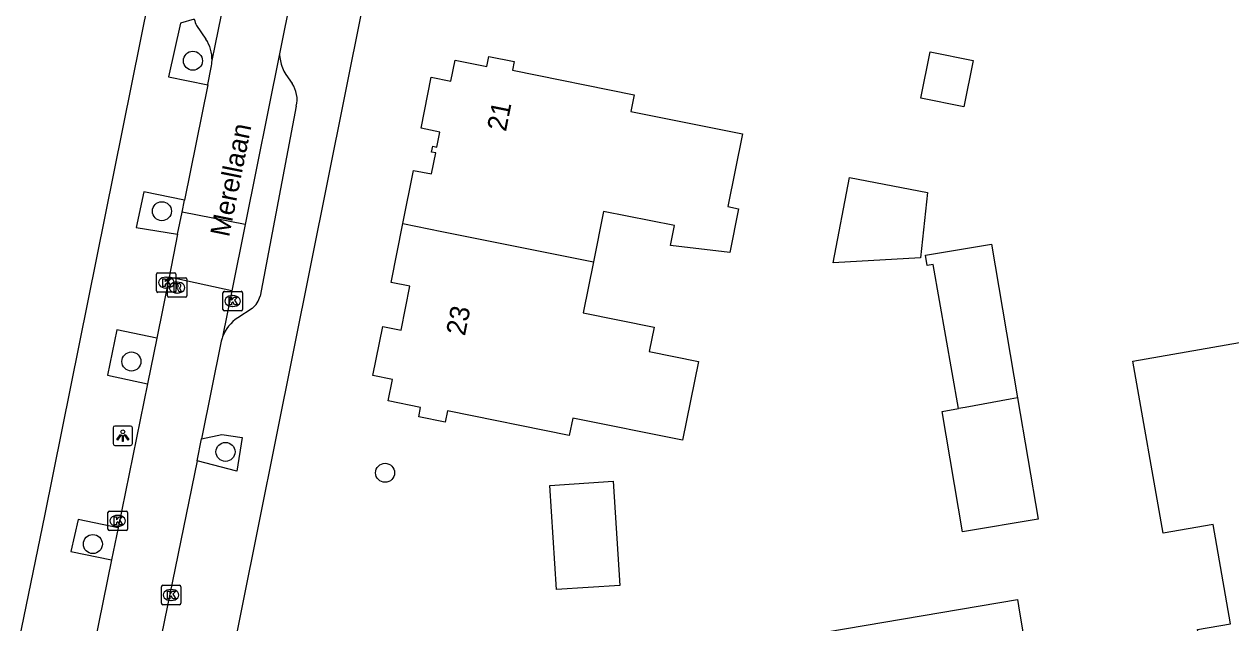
# Model space of a CAD drawing. Extents: x 161772 to 163123, y 383092 to 383917.
# Drawn here: x 162235.6 to 162297.6, y 383662.5 to 383693.3 of the extents above; entities that cross this region are included whole.
import ezdxf

# ---------------------------------------------------------------- set-up
doc = ezdxf.new("R2010")
doc.units = 0
for name, color, linetype in [('IMGEO_Boom', 7, 'Continuous'), ('IMGEO_Kolk', 7, 'Continuous'), ('IMGEO_Lichtpunt', 7, 'Continuous'), ('IMGEO_Openbare_ruimte_label', 7, 'Continuous'), ('IMGEO_Pand', 7, 'Continuous'), ('IMGEO_Pand_nummerreeks', 7, 'Continuous'), ('IMGEO_Parkeervlak_open', 7, 'Continuous'), ('IMGEO_Rijbaan_lokaal_open', 7, 'Continuous'), ('IMGEO_Rioolput', 7, 'Continuous'), ('IMGEO_Voetpad_open', 7, 'Continuous')]:
    doc.layers.add(name, color=color, linetype=linetype)

msp = doc.modelspace()

# ---------------------------------------------------------------- linework, layer by layer
at = {"layer": 'IMGEO_Boom'}
for centre in [(162244.252, 383691.425), (162242.659, 383683.691), (162241.091, 383675.965), (162245.927, 383671.318), (162254.126, 383670.243), (162239.112, 383666.581)]:
    msp.add_circle(centre, 0.489, dxfattribs=at)
at = {"layer": 'IMGEO_Kolk'}
for p, q in [((162242.38, 383679.595), (162242.38, 383680.447)), ((162242.455, 383680.521), (162243.307, 383680.521)), ((162243.381, 383680.447), (162243.381, 383679.595)), ((162242.868, 383680.301), (162242.893, 383680.301)), ((162243.307, 383679.521), (162242.455, 383679.521)), ((162242.891, 383679.741), (162242.866, 383679.741)), ((162245.797, 383678.646), (162245.797, 383679.498)), ((162245.872, 383679.572), (162246.724, 383679.572)), ((162246.285, 383679.352), (162246.31, 383679.352)), ((162246.798, 383679.498), (162246.798, 383678.646)), ((162246.724, 383678.572), (162245.872, 383678.572)), ((162246.308, 383678.792), (162246.283, 383678.792)), ((162239.887, 383667.347), (162239.887, 383668.199)), ((162239.962, 383668.273), (162240.814, 383668.273)), ((162240.375, 383668.053), (162240.4, 383668.053)), ((162240.888, 383668.199), (162240.888, 383667.347)), ((162240.398, 383667.493), (162240.373, 383667.493)), ((162240.814, 383667.273), (162239.962, 383667.273)), ((162242.63, 383663.535), (162242.63, 383664.387)), ((162242.705, 383664.461), (162243.557, 383664.461)), ((162243.631, 383664.387), (162243.631, 383663.535)), ((162243.141, 383663.681), (162243.116, 383663.681)), ((162243.118, 383664.241), (162243.143, 383664.241)), ((162243.557, 383663.461), (162242.705, 383663.461))]:
    msp.add_line(p, q, dxfattribs=at)
for points in [[(162242.38, 383679.595), (162242.38, 383680.447)], [(162242.455, 383680.521), (162243.307, 383680.521)], [(162243.381, 383680.447), (162243.381, 383679.595)], [(162242.701, 383680.221), (162242.824, 383680.221), (162242.824, 383680.07), (162242.954, 383680.221), (162243.118, 383680.221), (162242.972, 383680.07), (162243.125, 383679.821), (162242.973, 383679.821), (162242.888, 383679.985), (162242.824, 383679.918), (162242.824, 383679.821), (162242.701, 383679.821), (162242.701, 383680.221)], [(162243.307, 383679.521), (162242.455, 383679.521)], [(162245.797, 383678.646), (162245.797, 383679.498)], [(162245.872, 383679.572), (162246.724, 383679.572)], [(162246.118, 383679.272), (162246.241, 383679.272), (162246.241, 383679.121), (162246.371, 383679.272), (162246.535, 383679.272), (162246.389, 383679.121), (162246.542, 383678.872), (162246.39, 383678.872), (162246.305, 383679.036), (162246.241, 383678.969), (162246.241, 383678.872), (162246.118, 383678.872), (162246.118, 383679.272)], [(162246.798, 383679.498), (162246.798, 383678.646)], [(162246.724, 383678.572), (162245.872, 383678.572)], [(162239.887, 383667.347), (162239.887, 383668.199)], [(162239.962, 383668.273), (162240.814, 383668.273)], [(162240.888, 383668.199), (162240.888, 383667.347)], [(162240.208, 383667.973), (162240.331, 383667.973), (162240.331, 383667.822), (162240.461, 383667.973), (162240.625, 383667.973), (162240.479, 383667.822), (162240.632, 383667.573), (162240.48, 383667.573), (162240.395, 383667.737), (162240.331, 383667.67), (162240.331, 383667.573), (162240.208, 383667.573), (162240.208, 383667.973)], [(162240.814, 383667.273), (162239.962, 383667.273)], [(162242.63, 383663.535), (162242.63, 383664.387)], [(162242.705, 383664.461), (162243.557, 383664.461)], [(162243.631, 383664.387), (162243.631, 383663.535)], [(162242.951, 383664.161), (162243.074, 383664.161), (162243.074, 383664.01), (162243.204, 383664.161), (162243.368, 383664.161), (162243.222, 383664.01), (162243.375, 383663.761), (162243.223, 383663.761), (162243.138, 383663.925), (162243.074, 383663.858), (162243.074, 383663.761), (162242.951, 383663.761), (162242.951, 383664.161)], [(162243.557, 383663.461), (162242.705, 383663.461)]]:
    msp.add_lwpolyline(points, dxfattribs=at)
for centre, start, end in [((162242.457, 383680.445), 91.55205, 178.44795), ((162242.457, 383680.445), 91.55205, 178.44795), ((162243.305, 383680.445), 1.55205, 88.44795), ((162243.305, 383680.445), 1.55205, 88.44795), ((162242.457, 383679.597), 181.55205, 268.44795), ((162242.457, 383679.597), 181.55205, 268.44795), ((162243.305, 383679.597), 271.55205, 358.44795), ((162243.305, 383679.597), 271.55205, 358.44795), ((162245.874, 383679.496), 91.55205, 178.44795), ((162245.874, 383679.496), 91.55205, 178.44795), ((162246.722, 383679.496), 1.55205, 88.44795), ((162246.722, 383679.496), 1.55205, 88.44795), ((162245.874, 383678.648), 181.55205, 268.44795), ((162245.874, 383678.648), 181.55205, 268.44795), ((162246.722, 383678.648), 271.55205, 358.44795), ((162246.722, 383678.648), 271.55205, 358.44795), ((162239.964, 383668.197), 91.55205, 178.44795), ((162239.964, 383668.197), 91.55205, 178.44795), ((162240.812, 383668.197), 1.55205, 88.44795), ((162240.812, 383668.197), 1.55205, 88.44795), ((162239.964, 383667.349), 181.55205, 268.44795), ((162239.964, 383667.349), 181.55205, 268.44795), ((162240.812, 383667.349), 271.55205, 358.44795), ((162240.812, 383667.349), 271.55205, 358.44795), ((162242.707, 383664.385), 91.55205, 178.44795), ((162242.707, 383664.385), 91.55205, 178.44795), ((162243.555, 383664.385), 1.55205, 88.44795), ((162243.555, 383664.385), 1.55205, 88.44795), ((162242.707, 383663.537), 181.55205, 268.44795), ((162242.707, 383663.537), 181.55205, 268.44795), ((162243.555, 383663.537), 271.55205, 358.44795), ((162243.555, 383663.537), 271.55205, 358.44795)]:
    msp.add_arc(centre, 0.0765, start, end, dxfattribs=at)
for centre, major_axis, ratio, start_param, end_param in [((162242.867, 383680.021), (-0.387, 0.002), 0.722429, 4.712389, 7.853982), ((162242.892, 383680.021), (-0.39, 0.002), 0.717154, 1.570796, 4.712389), ((162246.284, 383679.072), (-0.387, 0.002), 0.722429, 4.712389, 7.853982), ((162246.309, 383679.072), (-0.39, 0.002), 0.717154, 1.570796, 4.712389), ((162240.374, 383667.773), (-0.387, 0.002), 0.722429, 4.712389, 7.853982), ((162240.399, 383667.773), (-0.39, 0.002), 0.717154, 1.570796, 4.712389), ((162243.117, 383663.961), (-0.387, 0.002), 0.722429, 4.712389, 7.853982), ((162243.142, 383663.961), (-0.39, 0.002), 0.717154, 1.570796, 4.712389)]:
    msp.add_ellipse(centre, major_axis=major_axis, ratio=ratio, start_param=start_param, end_param=end_param, dxfattribs=at)
at = {"layer": 'IMGEO_Lichtpunt'}
for p, q in [((162240.15, 383672.552), (162240.15, 383671.745)), ((162240.15, 383672.552), (162240.15, 383671.745)), ((162241.052, 383672.647), (162240.244, 383672.647)), ((162241.052, 383672.647), (162240.244, 383672.647)), ((162241.146, 383671.745), (162241.146, 383672.552)), ((162241.146, 383671.745), (162241.146, 383672.552)), ((162240.244, 383671.651), (162241.052, 383671.651)), ((162240.244, 383671.651), (162241.052, 383671.651))]:
    msp.add_line(p, q, dxfattribs=at)
for points in [[(162240.524, 383672.216), (162240.563, 383672.188), (162240.375, 383671.926), (162240.337, 383671.953), (162240.524, 383672.216)], [(162240.626, 383672.168), (162240.673, 383672.168), (162240.673, 383671.846), (162240.626, 383671.846), (162240.626, 383672.168)], [(162240.736, 383672.188), (162240.774, 383672.215), (162240.961, 383671.953), (162240.922, 383671.925), (162240.736, 383672.188)]]:
    msp.add_lwpolyline(points, dxfattribs=at)
msp.add_circle((162240.649, 383672.35), 0.0994, dxfattribs=at)
for centre, start, end in [((162240.244, 383672.552), 90, 180), ((162240.244, 383672.552), 90, 180), ((162241.052, 383672.552), 0, 90), ((162241.052, 383672.552), 0, 90), ((162240.244, 383671.745), 180, 270), ((162240.244, 383671.745), 180, 270), ((162241.052, 383671.745), 270, 0), ((162241.052, 383671.745), 270, 360)]:
    msp.add_arc(centre, 0.0946, start, end, dxfattribs=at)
at = {"layer": 'IMGEO_Pand'}
for points in [[(162255.047, 383683.053), (162255.595, 383685.789), (162256.516, 383685.604), (162256.733, 383686.684), (162256.517, 383686.728), (162256.578, 383687.031), (162256.793, 383686.988), (162256.948, 383687.76), (162255.973, 383687.955), (162256.5, 383690.583), (162257.509, 383690.381), (162257.724, 383691.449), (162259.354, 383691.122), (162259.458, 383691.641), (162260.762, 383691.379), (162260.673, 383690.936), (162266.927, 383689.681), (162266.756, 383688.825), (162272.486, 383687.676), (162271.735, 383683.929), (162272.292, 383683.818), (162271.84, 383681.562), (162268.794, 383681.931), (162268.999, 383682.953), (162265.353, 383683.684), (162264.833, 383681.092)], [(162282.129, 383691.885), (162284.349, 383691.44), (162283.871, 383689.053), (162281.65, 383689.498), (162282.129, 383691.885)], [(162281.996, 383684.661), (162281.636, 383681.302), (162277.15, 383681.032), (162277.984, 383685.427), (162281.996, 383684.661)], [(162264.833, 383681.092), (162264.305, 383678.459), (162267.954, 383677.727), (162267.704, 383676.478), (162270.23, 383675.972), (162269.417, 383671.922), (162263.768, 383673.055), (162263.59, 383672.169), (162257.338, 383673.423), (162257.221, 383672.84), (162255.856, 383673.114), (162255.955, 383673.608), (162254.293, 383673.941), (162254.513, 383675.034), (162253.503, 383675.237), (162254.009, 383677.756), (162254.946, 383677.568), (162255.401, 383679.836), (162254.441, 383680.029), (162255.047, 383683.053)], [(162255.047, 383683.053), (162257.039, 383682.655), (162264.833, 383681.092)], [(162283.593, 383673.547), (162282.287, 383680.953), (162281.99, 383680.901), (162281.901, 383681.431), (162285.291, 383682.004), (162286.628, 383674.091)], [(162307.651, 383682.214), (162308.927, 383674.919), (162305.994, 383674.406), (162306.24, 383673.004), (162306.907, 383673.12), (162306.917, 383673.064), (162309.3, 383659.431), (162303.773, 383658.465), (162304.013, 383657.092), (162299.587, 383656.307), (162299.345, 383657.691), (162298.46, 383657.536), (162298.313, 383658.375), (162296.597, 383658.075), (162295.878, 383662.189), (162297.568, 383662.485), (162296.678, 383667.583), (162294.103, 383667.133), (162292.555, 383675.979), (162301.449, 383677.535), (162300.839, 383681.022), (162307.651, 383682.214)], [(162286.628, 383674.091), (162287.68, 383667.867), (162283.803, 383667.212), (162282.758, 383673.397), (162283.593, 383673.547)], [(162286.628, 383674.091), (162286.252, 383674.024), (162283.931, 383673.608), (162283.593, 383673.547)], [(162266.193, 383664.449), (162262.933, 383664.24), (162262.589, 383669.595), (162265.848, 383669.805), (162266.193, 383664.449)], [(162276.641, 383656.972), (162275.808, 383661.901), (162286.624, 383663.728), (162286.734, 383663.083), (162288.495, 383652.653), (162289.327, 383647.722), (162289.081, 383647.518), (162289.37, 383645.807), (162288.885, 383645.126), (162285.651, 383644.579), (162284.932, 383645.091), (162284.643, 383646.805), (162284.396, 383646.763), (162284.315, 383647.242), (162278.457, 383646.253)]]:
    msp.add_lwpolyline(points, dxfattribs=at)
at = {"layer": 'IMGEO_Parkeervlak_open'}
msp.add_lwpolyline([(162244.443, 383693.231), (162244.918, 383692.537)], dxfattribs=at)
for centre, radius, start, end in [((162245.309, 383693.731), 1, 189.89365, 209.98839), ((162243.382, 383691.503), 1.852, 358.21998, 33.96165)]:
    msp.add_arc(centre, radius, start, end, dxfattribs=at)
at = {"layer": 'IMGEO_Rijbaan_lokaal_open'}
for points in [[(162245.233, 383691.445), (162247.616, 383703.103)], [(162250.518, 383700.823), (162248.704, 383691.779)], [(162248.704, 383691.779), (162246.938, 383683.014)], [(162245.011, 383690.184), (162245.016, 383690.209), (162245.185, 383691.074)], [(162245.011, 383690.184), (162243.826, 383684.256)], [(162243.7, 383683.645), (162243.826, 383684.256)], [(162243.465, 383682.513), (162243.7, 383683.645)], [(162246.938, 383683.014), (162243.7, 383683.645)], [(162246.938, 383683.014), (162246.25, 383679.596)], [(162243.465, 383682.513), (162243.028, 383680.299)], [(162243.028, 383680.299), (162242.391, 383677.172)], [(162246.25, 383679.596), (162243.028, 383680.299)], [(162246.25, 383679.596), (162245.773, 383677.227)], [(162242.391, 383677.172), (162241.911, 383674.82)], [(162245.702, 383677.002), (162244.695, 383671.995)], [(162241.911, 383674.82), (162240.415, 383667.412)], [(162244.462, 383670.857), (162244.695, 383671.995)], [(162244.462, 383670.857), (162242.496, 383661.241)], [(162240.415, 383667.412), (162240.076, 383665.771)], [(162240.076, 383665.771), (162238.342, 383657.247)]]:
    msp.add_lwpolyline(points, dxfattribs=at)
for centre, radius, start, end in [((162243.284, 383691.509), 1.95, 347.12472, 358.13132), ((162247.638, 383676.515), 1.996, 159.09914, 165.8741)]:
    msp.add_arc(centre, radius, start, end, dxfattribs=at)
at = {"layer": 'IMGEO_Rioolput'}
for p, q in [((162242.938, 383679.339), (162242.938, 383680.191)), ((162243.013, 383680.265), (162243.865, 383680.265)), ((162243.426, 383680.045), (162243.451, 383680.045)), ((162243.939, 383680.191), (162243.939, 383679.339)), ((162243.865, 383679.265), (162243.013, 383679.265)), ((162243.449, 383679.485), (162243.424, 383679.485))]:
    msp.add_line(p, q, dxfattribs=at)
for points in [[(162242.938, 383679.339), (162242.938, 383680.191)], [(162243.013, 383680.265), (162243.865, 383680.265)], [(162243.527, 383679.963), (162243.275, 383679.965), (162243.275, 383679.565)], [(162243.453, 383679.884), (162243.399, 383679.884), (162243.399, 383679.803)], [(162243.399, 383679.803), (162243.451, 383679.803)], [(162243.939, 383680.191), (162243.939, 383679.339)], [(162243.865, 383679.265), (162243.013, 383679.265)], [(162243.275, 383679.565), (162243.399, 383679.565), (162243.399, 383679.727), (162243.41, 383679.727)], [(162243.457, 383679.698), (162243.528, 383679.565), (162243.668, 383679.565), (162243.603, 383679.691)]]:
    msp.add_lwpolyline(points, dxfattribs=at)
for centre, radius, start, end in [((162243.015, 383680.189), 0.0765, 91.55205, 178.44795), ((162243.015, 383680.189), 0.0765, 91.55205, 178.44795), ((162243.435, 383679.992), 0.19, 274.7715, 282.96867), ((162243.459, 383679.788), 0.0964, 77.00612, 93.18647), ((162243.473, 383679.845), 0.0378, 276.66336, 79.67722), ((162243.526, 383679.853), 0.109, 350.36119, 89.41601), ((162243.524, 383679.853), 0.112, 277.58423, 350.98172), ((162243.863, 383680.189), 0.0765, 1.55205, 88.44795), ((162243.863, 383680.189), 0.0765, 1.55205, 88.44795), ((162243.015, 383679.341), 0.0765, 181.55205, 268.44795), ((162243.015, 383679.341), 0.0765, 181.55205, 268.44795), ((162243.409, 383679.674), 0.0533, 26.02933, 88.69889), ((162243.508, 383679.638), 0.108, 29.51342, 73.79051), ((162243.863, 383679.341), 0.0765, 271.55205, 358.44795), ((162243.863, 383679.341), 0.0765, 271.55205, 358.44795)]:
    msp.add_arc(centre, radius, start, end, dxfattribs=at)
for centre, major_axis, ratio, start_param, end_param in [((162243.425, 383679.765), (-0.387, 0.002), 0.722429, 4.712389, 7.853982), ((162243.45, 383679.765), (-0.39, 0.002), 0.717154, 1.570796, 4.712389)]:
    msp.add_ellipse(centre, major_axis=major_axis, ratio=ratio, start_param=start_param, end_param=end_param, dxfattribs=at)
at = {"layer": 'IMGEO_Voetpad_open'}
for points in [[(162259.685, 383782.554), (162253.133, 383750), (162236.634, 383668.028), (162228.473, 383628.501)], [(162255.603, 383707.378), (162240.556, 383632.345), (162241.527, 383630.611)], [(162244.324, 383693.559), (162243.613, 383693.357), (162243.001, 383690.593), (162245.011, 383690.184)], [(162249.021, 383690.724), (162249.352, 383690.254)], [(162249.566, 383689.085), (162247.704, 383679.331)], [(162243.826, 383684.256), (162241.736, 383684.69), (162241.335, 383682.862), (162243.465, 383682.513)], [(162247.29, 383678.695), (162246.559, 383678.215)], [(162242.391, 383677.172), (162240.343, 383677.594), (162239.866, 383675.27), (162241.911, 383674.82)], [(162244.695, 383671.995), (162245.741, 383672.219), (162246.776, 383672.055), (162246.513, 383670.331), (162244.462, 383670.857)], [(162240.415, 383667.412), (162238.349, 383667.847), (162237.975, 383666.205), (162240.076, 383665.771)]]:
    msp.add_lwpolyline(points, dxfattribs=at)
for centre, radius, start, end in [((162250.183, 383691.782), 1.479, 180.11981, 193.84887), ((162250.931, 383691.873), 2.228, 191.50708, 211.02535), ((162248.143, 383689.429), 1.464, 346.42537, 34.32231), ((162246.627, 383679.579), 1.106, 306.86517, 347.01113), ((162247.711, 383676.492), 2.073, 123.76718, 159.22505)]:
    msp.add_arc(centre, radius, start, end, dxfattribs=at)

# ---------------------------------------------------------------- texts
at = {"layer": 'IMGEO_Openbare_ruimte_label'}
msp.add_text('Merellaan', height=1, rotation=78.63386, dxfattribs=at).set_placement((162246.108, 383682.328))
at = {"layer": 'IMGEO_Pand_nummerreeks'}
for s, rotation, p in [('21', 78.7817, (162260.335, 383687.751)), ('23', 78.65606, (162258.227, 383677.247))]:
    msp.add_text(s, height=1, rotation=rotation, dxfattribs=at).set_placement(p)

doc.saveas('drawing.dxf')
